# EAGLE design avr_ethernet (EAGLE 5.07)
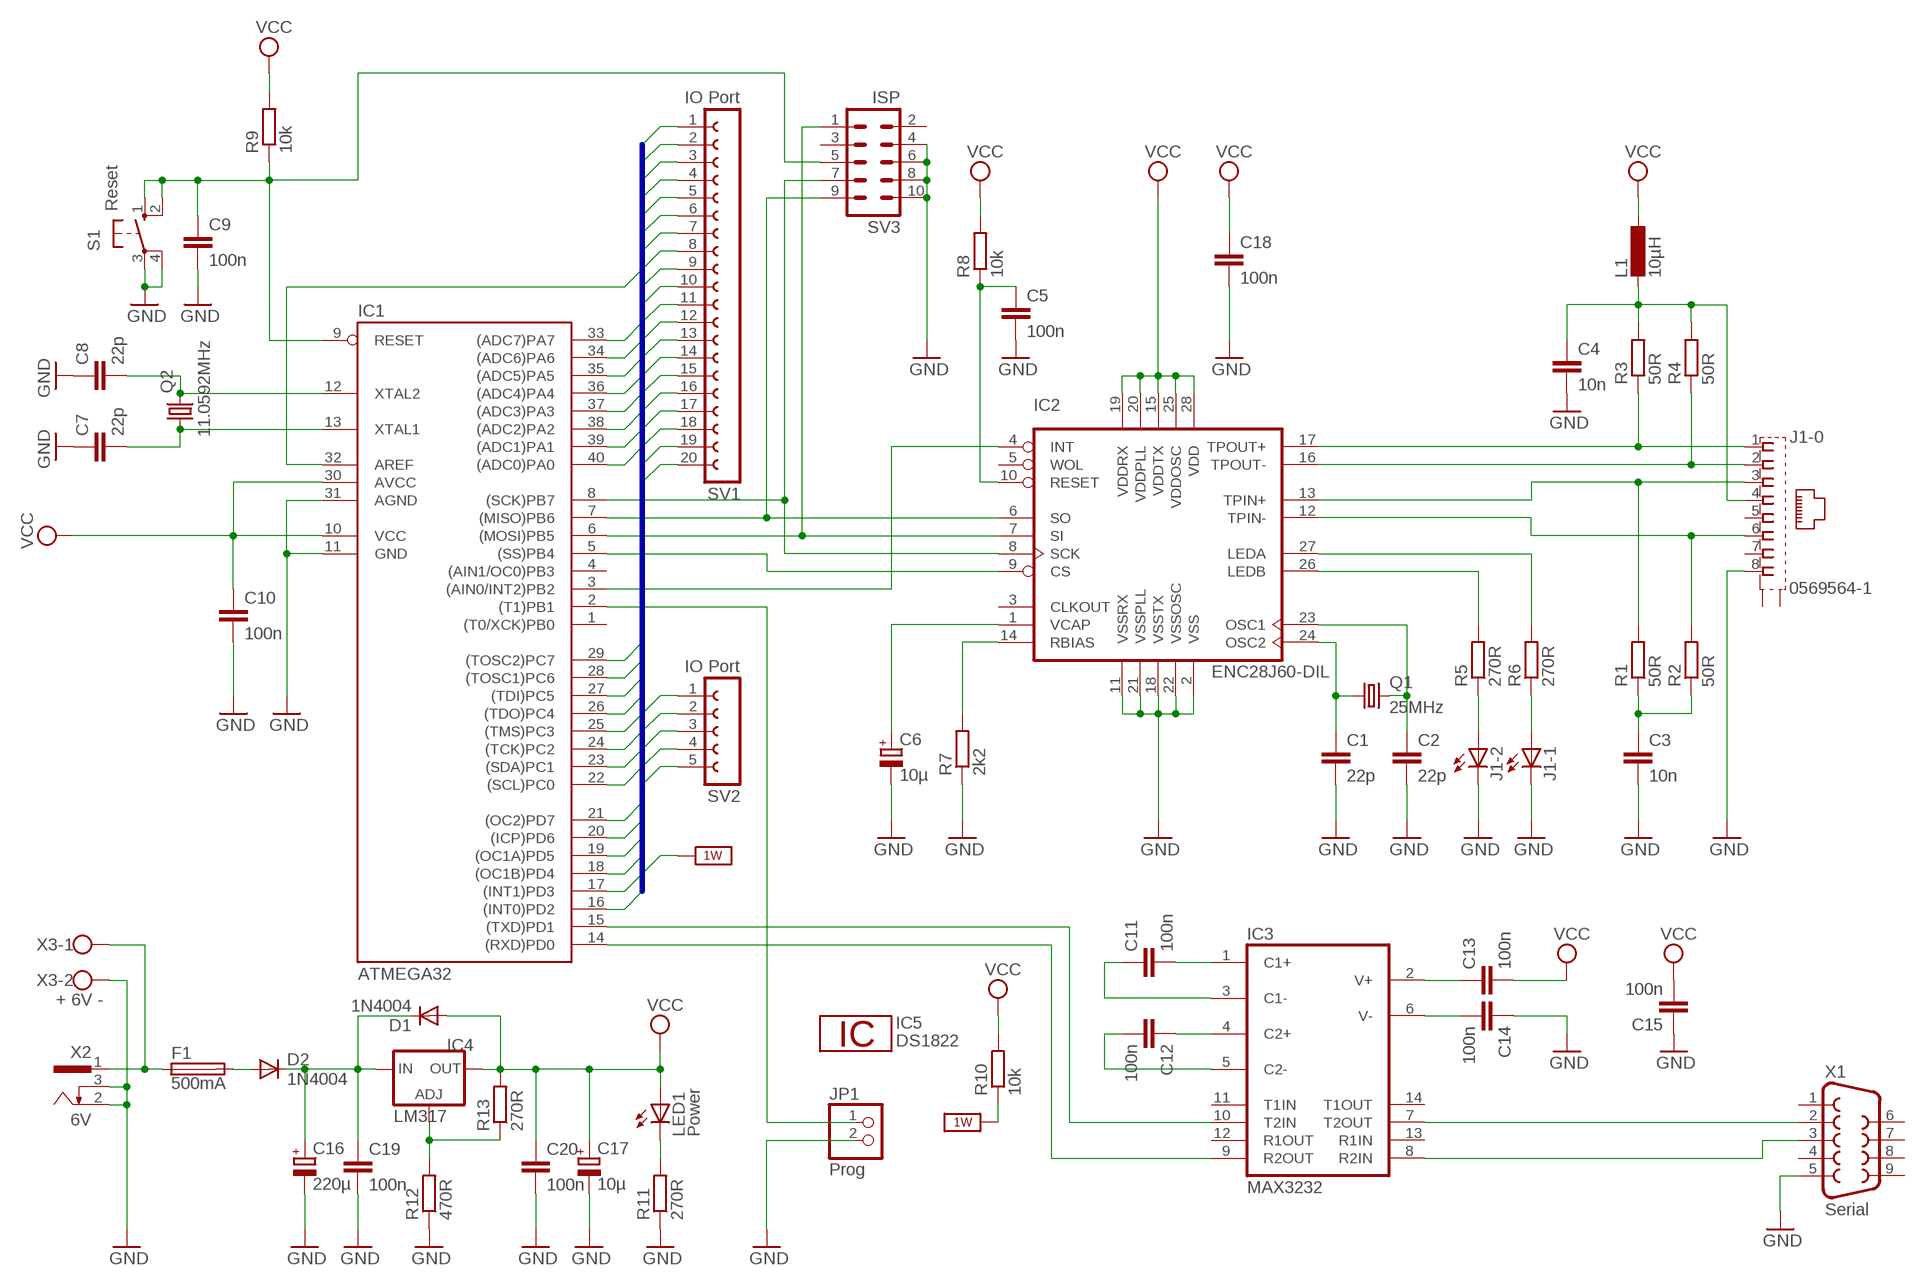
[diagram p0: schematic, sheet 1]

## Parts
C1  22p  C-EU025-025X050  [C025-025X050]
C2  22p  C-EU025-025X050  [C025-025X050]
C3  10n  C-EU025-025X050  [C025-025X050]
C4  10n  C-EU025-025X050  [C025-025X050]
C5  100n  C-EU025-025X050  [C025-025X050]
C6  10µ  CPOL-EUE2-5  [E2-5]
C7  22p  C-EU025-025X050  [C025-025X050]
C8  22p  C-EU025-025X050  [C025-025X050]
C9  100n  C-EU025-025X050  [C025-025X050]
C10  100n  C-EU025-025X050  [C025-025X050]
C11  100n  C-EU025-025X050  [C025-025X050]
C12  100n  C-EU025-025X050  [C025-025X050]
C13  100n  C-EU025-025X050  [C025-025X050]
C14  100n  C-EU025-025X050  [C025-025X050]
C15  100n  C-EU025-025X050  [C025-025X050]
C16  220µ  CPOL-EUE3.5-8  [E3,5-8]
C17  10µ  CPOL-EUE2-5  [E2-5]
C18  100n  C-EU025-025X050  [C025-025X050]
C19  100n  C-EU025-025X050  [C025-025X050]
C20  100n  C-EU025-025X050  [C025-025X050]
D1  1N4004  [DO41-10]
D2  1N4004  [DO41-10]
F1  500mA  PICOFUSE  [PICOFUSE]
IC1  ATMEGA32  MEGA32-P  [DIL40]
IC2  ENC28J60-DIL  [DIL28-3]
IC3  MAX3232  MAX232  [DIL16]
IC4  LM317  LM317TS  [317TS]
IC5  DS1822  [TO92-]
J1  0569564-1  [0569564]
JP1  Prog  PINHD-1X2  [1X02]
L1  10µH  L-EU0207/12  [0207/12]
LED1  Power  LED3MM  [LED3MM]
Q1  25MHz  CRYSTALHC49S  [HC49/S]
Q2  11.0592MHz  CRYSTALHC49S  [HC49/S]
R1  50R  R-EU_0207/10  [0207/10]
R2  50R  R-EU_0207/10  [0207/10]
R3  50R  R-EU_0207/10  [0207/10]
R4  50R  R-EU_0207/10  [0207/10]
R5  270R  R-EU_0207/10  [0207/10]
R6  270R  R-EU_0207/10  [0207/10]
R7  2k2  R-EU_0207/10  [0207/10]
R8  10k  R-EU_0207/12  [0207/12]
R9  10k  R-EU_0207/10  [0207/10]
R10  10k  R-EU_0207/10  [0207/10]
R11  270R  R-EU_0207/10  [0207/10]
R12  470R  R-EU_0207/10  [0207/10]
R13  270R  R-EU_0207/10  [0207/10]
S1  Reset  10-XX  [B3F-10XX]
SV1  IO Port  FE20-1  [FE20]
SV2  IO Port  FE05-1  [FE05-1]
SV3  ISP  ML10  [ML10]
X1  Serial  F09HP  [F09HP]
X2  6V  SCD-014A  [SCD-014-A]
X3  + 6V -  W237-102  [W237-102]

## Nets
1W: IC1.21((OC2)PD7) R10.1 SV1.20 ; supply symbol labelled 1W_SUP
AREF: IC1.32(AREF) SV1.9
GND: C1.2 C2.2 C3.2 C4.2 C5.2 C6.- C7.1 C8.1 C9.2 C10.2 C14.1 C15.1 C16.- C17.- C18.2 C19.2 C20.2 IC1.11(GND) IC1.31(AGND) IC2.2(VSS) IC2.11(VSSRX) IC2.18(VSSTX) IC2.21(VSSPLL) IC2.22(VSSOSC) J1.8 J1.C1(-1:C) J1.C2(-2:C) JP1.2 R7.1 R11.1 R12.1 S1.3(P) S1.4(P1) SV1.10 SV3.4 SV3.6 SV3.8 SV3.10 X1.5 X2.2 X2.3 X3.2
N$1: IC1.7((MISO)PB6) IC2.6(SO) SV3.9
N$2: IC1.6((MOSI)PB5) IC2.7(SI) SV3.1
N$3: IC1.8((SCK)PB7) IC2.8(SCK) SV3.7
N$4: IC2.17(TPOUT+) J1.1 R3.1
N$5: IC2.16(TPOUT-) J1.2 R4.1
N$6: IC2.13(TPIN+) J1.3 R1.2
N$7: IC2.12(TPIN-) J1.6 R2.2
N$8: C4.1 J1.4 L1.2 R3.2 R4.2
N$9: J1.A2(-2:A) R5.1
N$10: C3.1 R1.1 R2.1
N$11: J1.A1(-1:A) R6.1
N$12: IC2.26(LEDB) R5.2
N$13: IC2.27(LEDA) R6.2
N$14: C6.+ IC2.1(VCAP)
N$15: IC2.14(RBIAS) R7.2
N$16: IC1.3((AIN0/INT2)PB2) IC2.4(INT)
N$17: C1.1 IC2.24(OSC2) Q1.1
N$18: C2.1 IC2.23(OSC1) Q1.2
N$19: C5.1 IC2.10(RESET) R8.1
N$20: IC1.5((SS)PB4) IC2.9(CS)
N$21: C9.1 IC1.9(RESET) R9.1 S1.1(S) S1.2(S1) SV3.5
N$22: C7.2 IC1.13(XTAL1) Q2.1
N$23: C8.2 IC1.12(XTAL2) Q2.2
N$25: IC3.7(T2OUT) X1.2
N$26: IC3.8(R2IN) X1.3
N$27: C13.1 IC3.2(V+)
N$28: C14.2 IC3.6(V-)
N$30: C11.2 IC3.1(C1+)
N$31: C11.1 IC3.3(C1-)
N$32: C12.1 IC3.4(C2+)
N$33: C12.2 IC3.5(C2-)
N$34: IC1.15((TXD)PD1) IC3.10(T2IN)
N$35: IC1.14((RXD)PD0) IC3.9(R2OUT)
N$37: IC1.2((T1)PB1) JP1.1
N$42: D2.A F1.2
N$54: LED1.K(C) R11.2
N$55: F1.1 X2.1 X3.1
N$56: C16.+ C19.1 D1.C D2.C IC4.3(IN)
N$60: IC4.1(ADJ) R12.2 R13.1
PA0: IC1.40((ADC0)PA0) SV1.1
PA1: IC1.39((ADC1)PA1) SV1.2
PA2: IC1.38((ADC2)PA2) SV1.3
PA3: IC1.37((ADC3)PA3) SV1.4
PA4: IC1.36((ADC4)PA4) SV1.5
PA5: IC1.35((ADC5)PA5) SV1.6
PA6: IC1.34((ADC6)PA6) SV1.7
PA7: IC1.33((ADC7)PA7) SV1.8
PC0: IC1.22((SCL)PC0) SV1.19
PC1: IC1.23((SDA)PC1) SV1.18
PC2: IC1.24((TCK)PC2) SV1.17
PC3: IC1.25((TMS)PC3) SV1.16
PC4: IC1.26((TDO)PC4) SV1.15
PC5: IC1.27((TDI)PC5) SV1.14
PC6: IC1.28((TOSC1)PC6) SV1.13
PC7: IC1.29((TOSC2)PC7) SV1.12
PD2: IC1.16((INT0)PD2) SV2.1
PD3: IC1.17((INT1)PD3) SV2.2
PD4: IC1.18((OC1B)PD4) SV2.3
PD5: IC1.19((OC1A)PD5) SV2.4
PD6: IC1.20((ICP)PD6) SV2.5
VCC: C10.1 C13.2 C15.2 C17.+ C18.1 C20.1 D1.A IC1.10(VCC) IC1.30(AVCC) IC2.15(VDDTX) IC2.19(VDDRX) IC2.20(VDDPLL) IC2.25(VDDOSC) IC2.28(VDD) IC4.2(OUT) L1.1 LED1.A R8.2 R9.2 R10.2 R13.2 SV1.11
Unconnected: IC1.1((T0/XCK)PB0) IC1.4((AIN1/OC0)PB3) IC2.3(CLKOUT) IC2.5(WOL) IC3.11(T1IN) IC3.12(R1OUT) IC3.13(R1IN) IC3.14(T1OUT) J1.5 J1.7 J1.S1(-0:S1) J1.S2(-0:S2) SV3.2 SV3.3 X1.1 X1.4 X1.6 X1.7 X1.8 X1.9

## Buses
B$1:PA0,PA1,PA2,PA3,PA4,PA5,PA6,PA7,PC0,PC1,PC2,PC3,PC4,PC5,PC6,PC7,PD2,PD3,PD4,PD5,PD6,GND,VCC,AREF,1W

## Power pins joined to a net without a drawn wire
1W: IC5.2
GND: IC3.15(GND) IC5.1
VCC: IC3.16(VCC) IC5.3

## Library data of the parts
C1-C5 C7-C15 C18-C20 = rcl:C-EU: CAPACITOR, European symbol
C6 C16 C17 = rcl:CPOL-EU: POLARIZED CAPACITOR, European symbol
D1 D2 = diode:1N4004: DIODE
F1 = fuse:PICOFUSE: PICOFUSE
IC1 = atmel:MEGA32-P: MICROCONTROLLER 32 Kbytes FLASH 2 Kbytes SRAM 1 Kbytes EEPROM USART 8-channel 10 bit ADC Source: www.atmel.com .. doc2503.pdf
IC2 = microchip-enc28j60:ENC28J60-*: Microchip 10Mbit Eth. contoller with SPI interface
IC3 = maxim:MAX232: RS232 TRANSEIVER
IC4 = v-reg:LM317TS: VOLTAGE REGULATOR
IC5 = 1wire:DS1822: Econo Digital Thermometer This chip provides a onewire thermosensor with approx. 2°C accuracy. A programmable over/undertemperure alarm is available. Notes: Vdd must be applied for accurate measurements at low temperatures, as the parasite power circuit otherwise heats the sensor. If parasite power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
J1 = con-amp:0569564-*: MODULAR JACK 8 POS., RIGHT ANGLE, LOW PROFILE WITH LEDS Source: http://ecommas.tycoelectronics.com/.. 569564_K.pdf
JP1 = pinhead:PINHD-1X2: PIN HEADER
L1 = rcl:L-EU: INDUCTOR, European symbol
LED1 = led:LED: LED
Q1 Q2 = crystal:CRYSTAL: CRYSTAL
R1-R13 = rcl:R-EU_: RESISTOR, European symbol
S1 = switch-omron:10-XX: OMRON SWITCH
SV1 = con-lsta:FE20-1: FEMALE HEADER
SV2 = con-lsta:FE05-1: FEMALE HEADER
SV3 = con-harting-ml:ML10: HARTING
X1 = con-subd:F09: SUB-D
X2 = con-shiua-chyuan:SCD-014A: Power Jack 2.5mm
X3 = con-wago-500:W237-102: WAGO SCREW CLAMP

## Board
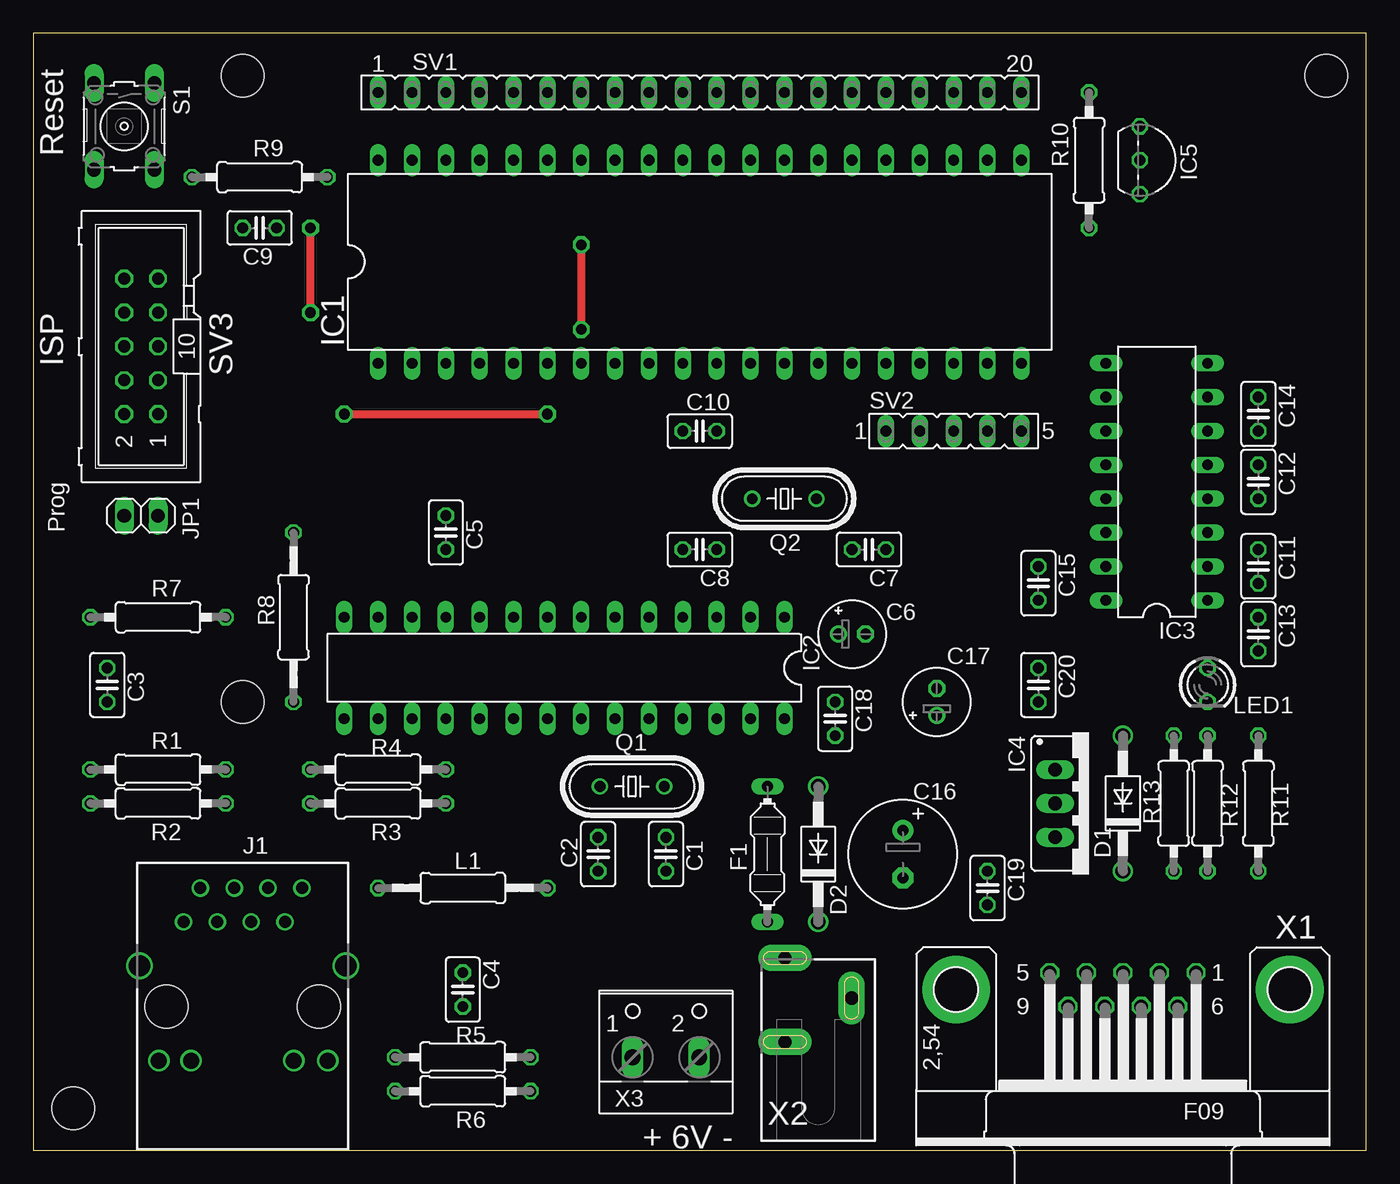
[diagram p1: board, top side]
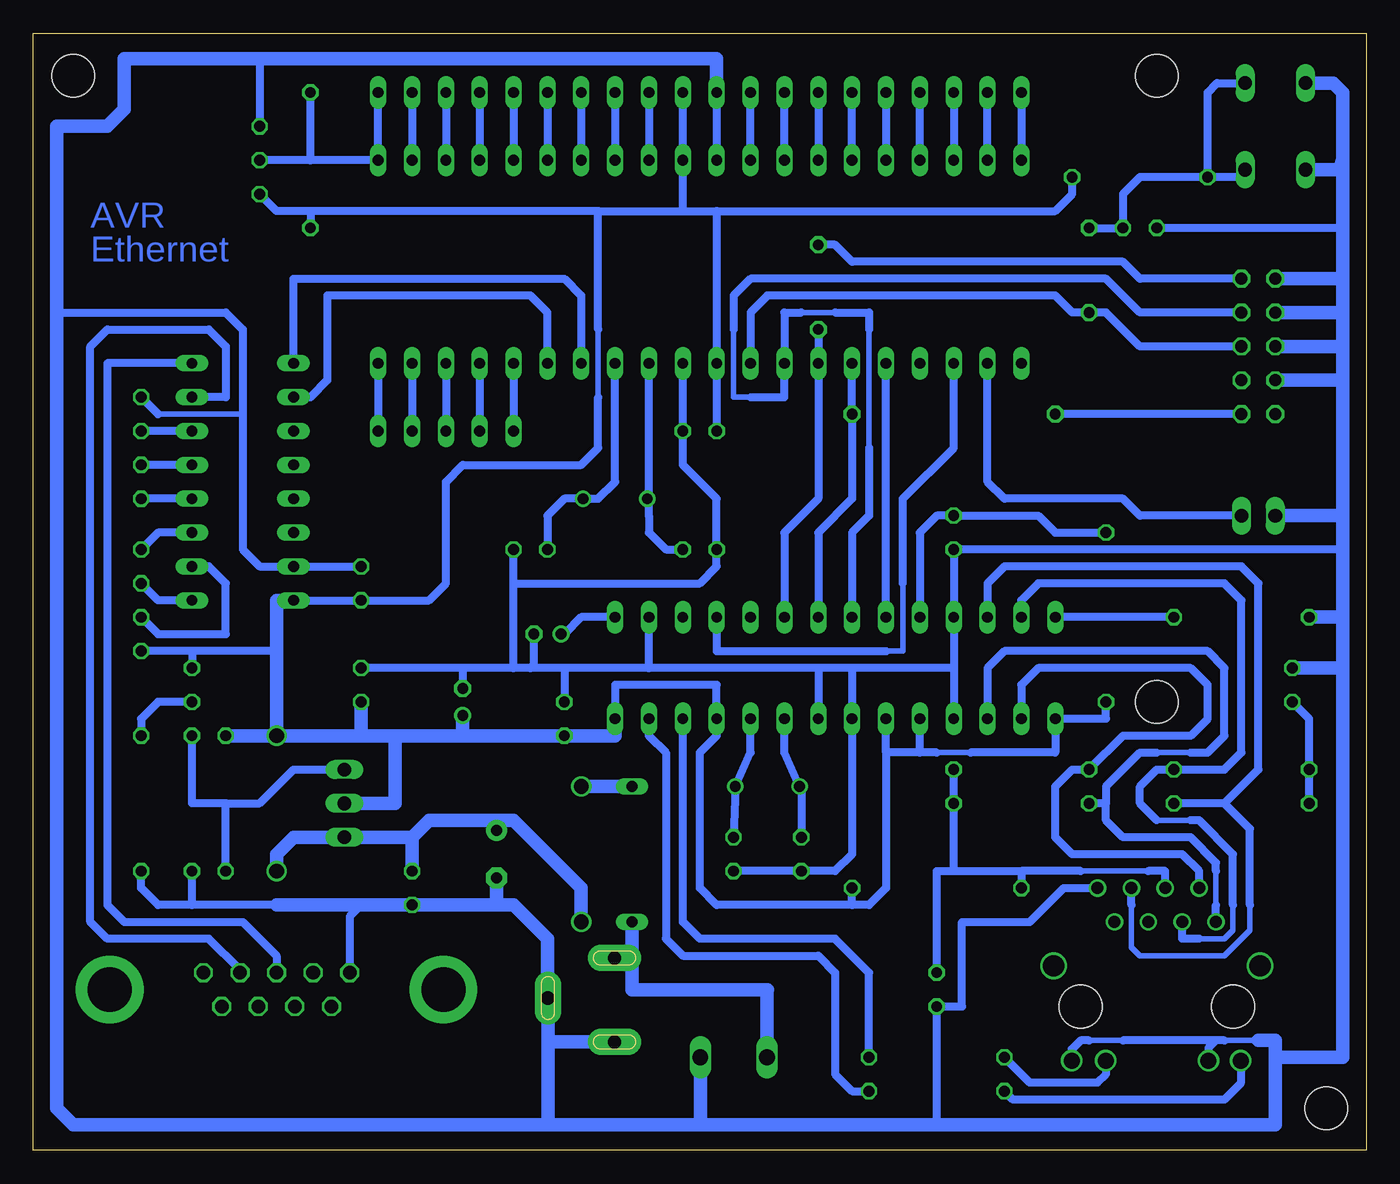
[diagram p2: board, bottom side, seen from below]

Size 100 x 83.81 mm. Coordinates in mm from the lower left corner, seen from the top.
Outline: 0,0 100,0 100,83.81 0,83.81 0,0
Copper layers (1*16): Top 0.035mm / dielectric 1.5mm / Bottom 0.035mm
Design rules "PCB-POOL": minimum track width 6mil, minimum drill 12mil, track to track 6mil, track to pad 6mil, pad to pad 6mil, via to via 6mil, smd to smd 6mil, copper to edge 20mil, drill to drill 8mil, minimum pad ring 8mil, minimum via ring 6mil, stop-mask expansion 3mil, vias tented up to drill 0mil, thermal gap 8mil
Holes 3.2 mm at 3.01,3.17 96.99,80.64 15.71,80.64 15.71,33.65

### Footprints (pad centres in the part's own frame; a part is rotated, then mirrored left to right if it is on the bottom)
C025-025X050 = drill 0.813 octagon: 1 -1.27,0; 2 1.27,0
E2-5 = drill 0.813 pad 1.27 round: + -1.016,0 | drill 0.813 pad 1.27 octagon: - 1.016,0
E3,5-8 = drill 0.813 pad 1.6 round: + -1.778,0 | drill 0.813 pad 1.6 octagon: - 1.778,0
DO41-10 = drill 1.118 round: A 5.08,0; C -5.08,0
PICOFUSE = drill 0.813 long: 1 -5.08,0; 2 5.08,0
DIL40 = drill 0.813 long: 1 -24.13,-7.62; 2 -21.59,-7.62; 3 -19.05,-7.62; 4 -16.51,-7.62; 5 -13.97,-7.62; 6 -11.43,-7.62; 7 -8.89,-7.62; 8 -6.35,-7.62; 9 -3.81,-7.62; 10 -1.27,-7.62; 11 1.27,-7.62; 12 3.81,-7.62; 13 6.35,-7.62; 14 8.89,-7.62; 15 11.43,-7.62; 16 13.97,-7.62; 17 16.51,-7.62; 18 19.05,-7.62; 19 21.59,-7.62; 20 24.13,-7.62; 21 24.13,7.62; 22 21.59,7.62; 23 19.05,7.62; 24 16.51,7.62; 25 13.97,7.62; 26 11.43,7.62; 27 8.89,7.62; 28 6.35,7.62; 29 3.81,7.62; 30 1.27,7.62; 31 -1.27,7.62; 32 -3.81,7.62; 33 -6.35,7.62; 34 -8.89,7.62; 35 -11.43,7.62; 36 -13.97,7.62; 37 -16.51,7.62; 38 -19.05,7.62; 39 -21.59,7.62; 40 -24.13,7.62
DIL28-3 = drill 0.813 long: 1 -16.51,-3.81; 2 -13.97,-3.81; 3 -11.43,-3.81; 4 -8.89,-3.81; 5 -6.35,-3.81; 6 -3.81,-3.81; 7 -1.27,-3.81; 8 1.27,-3.81; 9 3.81,-3.81; 10 6.35,-3.81; 11 8.89,-3.81; 12 11.43,-3.81; 13 13.97,-3.81; 14 16.51,-3.81; 15 16.51,3.81; 16 13.97,3.81; 17 11.43,3.81; 18 8.89,3.81; 19 6.35,3.81; 20 3.81,3.81; 21 1.27,3.81; 22 -1.27,3.81; 23 -3.81,3.81; 24 -6.35,3.81; 25 -8.89,3.81; 26 -11.43,3.81; 27 -13.97,3.81; 28 -16.51,3.81
DIL16 = drill 0.813 long: 1 -8.89,-3.81; 2 -6.35,-3.81; 3 -3.81,-3.81; 4 -1.27,-3.81; 5 1.27,-3.81; 6 3.81,-3.81; 7 6.35,-3.81; 8 8.89,-3.81; 9 8.89,3.81; 10 6.35,3.81; 11 3.81,3.81; 12 1.27,3.81; 13 -1.27,3.81; 14 -3.81,3.81; 15 -6.35,3.81; 16 -8.89,3.81
317TS = drill 1.016 long: 1 -2.54,-2.54; 2 0,-2.54; 3 2.54,-2.54
TO92- = drill 0.813 octagon: 1 -2.54,0; 2 0,0; 3 2.54,0
0569564 = drill 0.9 round: 1 -4.445,6.35; 2 -3.175,8.89; 3 -1.905,6.35; 4 -0.635,8.89; 5 0.635,6.35; 6 1.905,8.89; 7 3.175,6.35; 8 4.445,8.89 | drill 1.2 round: A1 -6.295,-4.066; A2 3.835,-4.066; C1 -3.882,-4.06; C2 6.375,-4.06 | drill 1.6 round: S1 -7.745,3.05; S2 7.745,3.05 | hole 3.25: -5.715,0; 5.715,0
1X02 = drill 1.016 long: 1 -1.27,0; 2 1.27,0
0207/12 = drill 0.813 octagon: 1 -6.35,0; 2 6.35,0
LED3MM = drill 0.813 octagon: A -1.27,0; K 1.27,0
HC49/S = drill 0.813 round: 1 -2.413,0; 2 2.413,0
0207/10 = drill 0.813 octagon: 1 -5.08,0; 2 5.08,0
B3F-10XX = drill 1.016 long: 1 -3.251,2.261; 2 3.251,2.261; 3 -3.251,-2.261; 4 3.251,-2.261
FE20 = drill 0.813 long: 1 -24.13,0; 2 -21.59,0; 3 -19.05,0; 4 -16.51,0; 5 -13.97,0; 6 -11.43,0; 7 -8.89,0; 8 -6.35,0; 9 -3.81,0; 10 -1.27,0; 11 1.27,0; 12 3.81,0; 13 6.35,0; 14 8.89,0; 15 11.43,0; 16 13.97,0; 17 16.51,0; 18 19.05,0; 19 21.59,0; 20 24.13,0
FE05-1 = drill 0.813 long: 1 -5.08,0; 2 -2.54,0; 3 0,0; 4 2.54,0; 5 5.08,0
ML10 = drill 0.914 octagon: 1 -5.08,-1.27; 2 -5.08,1.27; 3 -2.54,-1.27; 4 -2.54,1.27; 5 0,-1.27; 6 0,1.27; 7 2.54,-1.27; 8 2.54,1.27; 9 5.08,-1.27; 10 5.08,1.27
F09HP = drill 1.016 octagon: 1 -5.486,-1.27; 2 -2.743,-1.27; 3 0,-1.27; 4 2.743,-1.27; 5 5.486,-1.27; 6 -4.115,1.27; 7 -1.372,1.27; 8 1.372,1.27; 9 4.115,1.27 | drill 3.302 pad 5.08 round: G1 -12.522,0; G2 12.522,0
SCD-014-A = drill 1 pad 2 long: 1 -2.5,13.8; 2 -2.5,7.5; 3 2.5,10.8
W237-102 = drill 1.194 long: 1 -2.5,-1.27; 2 2.5,-1.27

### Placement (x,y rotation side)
C1  47.46,22.22 270 top
C2  42.38,22.22 270 top
C3  5.55,34.92 90 top
C4  32.22,12.06 270 top
C5  30.95,46.35 270 top
C6  61.43,38.73 0 top
C7  62.7,45.08 180 top
C8  50,45.08 0 top
C9  16.98,69.21 180 top
C10  50,53.97 0 top
C11  91.91,43.81 270 top
C12  91.91,50.16 90 top
C13  91.91,38.73 270 top
C14  91.91,55.24 270 top
C15  75.4,42.54 270 top
C16  65.24,22.22 270 top
C17  67.78,33.65 90 top
C18  60.16,32.38 90 top
C19  71.59,19.68 270 top
C20  75.4,34.92 90 top
D1  81.75,26.03 90 top
D2  58.89,22.22 90 top
F1  55.08,22.22 90 top
IC1  50,66.67 0 top
IC2  39.84,36.19 180 top
IC3  84.29,50.16 90 top
IC4  79.21,26.03 270 top
IC5  83.02,74.29 270 top
J1  15.71,10.79 0 top
JP1  8.09,47.62 180 top
L1  32.22,19.68 180 top
LED1  88.1,34.92 270 top
Q1  44.92,27.3 180 top
Q2  56.35,48.89 180 top
R1  9.36,28.57 0 top
R2  9.36,26.03 0 top
R3  25.87,26.03 0 top
R4  25.87,28.57 0 top
R5  32.22,6.98 0 top
R6  32.22,4.44 0 top
R7  9.36,40 0 top
R8  19.52,40 270 top
R9  16.98,73.02 0 top
R10  79.21,74.29 270 top
R11  91.91,26.03 90 top
R12  88.1,26.03 90 top
R13  85.56,26.03 90 top
S1  6.82,76.83 270 top
SV1  50,79.37 0 top
SV2  69.05,53.97 0 top
SV3  8.09,60.32 90 top
X1  81.75,12.06 180 top
X2  58.89,0.63 0 top
X3  47.46,8.25 0 top

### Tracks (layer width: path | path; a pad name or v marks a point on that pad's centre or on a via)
1W
  Bottom 0.61: 79.21,74.29 IC5.2 | 79.21,74.29 R10.1 | 79.21,74.29 IC1.21 SV1.20
AREF
  Bottom 0.61: IC1.32 SV1.9
GND
  Bottom 0.406: 30.95,36.19 IC2.11 | X2.3 61.39,10.79 61.43,10.79 | 65.24,1.9 61.39,1.94 | 61.39,8.25 61.43,8.25 61.31,8.13 | 84.29,55.24 90.64,55.24 | 1.74,75.56 2.3,73.58 | 8.09,8.25 10.63,8.25 | 18.25,8.25 20.79,8.25 | IC3.15 C15.1
  Bottom 0.61: 32.22,1.9 C4.2 30.31,10.79 30.31,17.14 25.23,17.14 22.7,19.68 J1.8 | 41.11,36.19 IC2.22 | 38.57,36.19 41.11,36.19 | C1.2 C2.2 39.84,20.95 38.57,22.22 IC2.21 38.57,36.19 | 30.95,36.19 IC2.18 | 41.11,36.19 53.81,36.19 | 53.81,36.19 60.16,36.19 | 53.81,36.19 IC2.2 | 60.16,36.19 C18.2 | 63.97,42.54 50,42.54 48.73,43.81 C8.1 48.73,48.89 51.27,51.43 C10.2 IC1.11 | 63.97,42.54 C7.1 | 63.97,36.19 63.97,42.54 | 30.95,36.19 38.57,36.19 | 30.95,36.19 C5.2 1.74,45.08 | 90.64,55.24 C14.1 | 98.26,62.86 85.56,62.86 84.29,61.59 84.29,55.24 84.29,45.08 83.02,43.81 IC3.15 C15.1 | R11.1 91.91,19.68 90.64,18.41 88.1,18.41 | 81.75,18.41 88.1,18.41 | 88.1,18.41 R12.1 | 60.16,36.19 62.7,36.19 | 62.7,36.19 63.97,36.19 | 63.97,36.19 67.78,36.19 | 67.78,36.19 C17.- | 67.78,36.19 C20.2 | C6.- 62.45,36.44 62.7,36.19 | J1.C2 22.08,7.59 21.42,8.25 20.79,8.25 | 10.63,8.25 11.27,8.25 | 11.27,8.25 18.25,8.25 | J1.C1 11.83,7.69 11.27,8.25 | X1.5 76.26,17.55 75.4,18.41 | 83.02,81.91 IC5.1 | 1.74,69.21 C9.2 | SV1.10 IC1.31
  Bottom 1.016: 1.74,36.19 C3.2 | 1.74,40 1.74,45.08 1.74,47.62 | 1.74,40 R7.1 | 1.74,36.19 1.74,40 | 50,1.9 32.22,1.9 6.82,1.9 6.82,6.98 | 50,1.9 65.24,1.9 96.99,1.9 98.26,3.17 98.26,62.86 98.26,76.83 94.45,76.83 93.18,78.1 93.18,81.91 83.02,81.91 48.73,81.91 SV1.10 | 61.39,1.94 61.39,8.25 61.39,10.79 | 61.31,8.13 X2.2 | 63.97,18.41 65.24,18.41 C16.- | 61.43,10.79 61.43,15.87 63.97,18.41 | 63.97,18.41 C19.2 75.4,18.41 81.75,18.41 | S1.3 2.45,80.08 1.74,79.37 1.74,75.56 1.74,69.21 1.74,65.4 | 1.74,47.62 1.74,57.78 | 1.74,57.78 1.74,60.32 | 1.74,60.32 1.74,62.86 | 1.74,62.86 1.74,65.4 | 2.3,73.58 S1.4 | 1.74,65.4 SV3.10 | 1.74,62.86 SV3.8 | 1.74,60.32 SV3.6 | 1.74,57.78 SV3.4 | 1.74,47.62 JP1.2 | X3.2 49.96,1.94 50,1.9 | 6.82,6.98 1.74,6.98 1.74,36.19 | 8.09,8.25 6.82,8.25 6.82,6.98
N$1  (via drill 0.8 pad 1.27)
  Top 0.61: v41.11,67.94 v41.11,61.59
  Bottom 0.61: IC2.6 43.65,46.35 41.11,48.89 IC1.7 v41.11,61.59 | SV3.9 16.98,65.4 18.25,66.67 38.57,66.67 39.84,67.94 v41.11,67.94
N$2  (via drill 0.8 pad 1.27)
  Top 0.61: v23.33,55.24 v38.57,55.24
  Bottom 0.61: IC2.7 41.11,46.35 38.57,48.89 v38.57,55.24 IC1.6 | SV3.1 v23.33,55.24
N$3
  Bottom 0.406: 37.3,61.59 37.3,52.7 | 42.38,62.86 39.84,62.86 | 46.19,56.51 47.46,56.51 47.46,61.59
  Bottom 0.61: IC2.8 38.57,46.35 37.3,47.62 37.3,52.7 | 37.3,61.59 37.3,62.86 39.84,62.86 | 42.38,62.86 43.65,62.86 IC1.8 43.65,56.51 46.19,56.51 | 47.46,61.59 47.46,64.13 46.19,65.4 19.52,65.4 16.98,62.86 SV3.7
N$4
  Bottom 0.406: 15.71,29.84 13.17,29.84 | 11.27,18.41 11.27,20.95
  Bottom 0.61: 19.52,26.03 R3.1 | 19.52,26.03 19.52,27.3 16.98,29.84 15.71,29.84 | 13.17,29.84 11.9,29.84 10.63,31.11 10.63,36.19 11.9,37.46 27.14,37.46 28.41,36.19 IC2.17 | J1.1 11.27,18.41 | 11.27,20.95 11.27,21.58 13.17,23.49 18.25,23.49 19.52,24.76 19.52,26.03
N$5
  Bottom 0.61: IC2.16 25.87,34.92 24.6,36.19 13.17,36.19 11.9,34.92 11.9,32.38 13.17,31.11 18.25,31.11 R4.1 22.06,28.57 23.33,27.3 23.33,23.49 22.06,22.22 13.81,22.22 12.54,20.95 J1.2
N$6
  Bottom 0.406: 12.54,15.87 10.63,15.87 10,16.5 10,18.41 | 13.17,24.76 15.71,24.76
  Bottom 0.61: IC2.13 25.87,41.27 24.6,42.54 10.63,42.54 9.36,41.27 9.36,29.84 10.63,28.57 R1.2 15.71,28.57 16.98,27.3 16.98,26.03 15.71,24.76 | J1.3 13.81,15.87 12.54,15.87 | 10,18.41 10,22.22 12.54,24.76 13.17,24.76
N$7
  Bottom 0.406: 17.61,18.41 17.61,15.24 16.98,14.6 10.63,14.6 8.73,16.5 8.73,18.41
  Bottom 0.61: 10.63,26.03 8.09,28.57 8.09,42.54 9.36,43.81 27.14,43.81 28.41,42.54 IC2.12 | 10.63,26.03 R2.2 | 17.61,18.41 J1.6 | 8.73,18.41 8.73,24.12 10.63,26.03
N$8
  Bottom 0.406: 16.34,20.95 21.42,20.95
  Bottom 0.61: 30.95,20.95 32.22,20.95 C4.1 | 30.95,20.95 R3.2 R4.2 | 25.87,20.95 L1.2 | 30.95,20.95 25.87,20.95 | J1.4 15.08,20.95 16.34,20.95 | 21.42,20.95 25.87,20.95
N$9
  Bottom 0.61: J1.A2 19.54,5.68 20.15,5.08 25.23,5.08 R5.1
N$10
  Bottom 0.61: R2.1 R1.1 4.28,32.38 C3.1
N$11
  Bottom 0.61: J1.A1 9.42,5.02 10.63,3.8 26.5,3.8 R6.1
N$12
  Bottom 0.61: R5.2 37.3,13.33 39.84,15.87 50,15.87 51.27,17.14 IC2.26
N$13
  Bottom 0.61: IC2.27 53.81,31.11 52.54,29.84 52.54,15.87 51.27,14.6 41.11,14.6 39.84,13.33 39.84,5.71 38.57,4.44 R6.2
N$14
  Bottom 0.61: IC2.1 58.89,40 60.16,38.73 C6.+
N$15
  Bottom 0.61: R7.2 IC2.14
N$16
  Bottom 0.406: 36.03,37.46 34.76,37.46 34.76,42.54
  Bottom 0.61: IC2.4 48.73,37.46 36.03,37.46 | 34.76,42.54 34.76,48.89 30.95,52.7 IC1.3
N$17
  Bottom 0.61: IC2.24 46.19,29.84 Q1.1 C1.1
N$18
  Bottom 0.61: IC2.23 43.65,29.84 Q1.2 42.38,27.3 C2.1
N$19
  Bottom 0.61: IC2.10 33.49,46.35 32.22,47.62 C5.1 24.6,47.62 23.33,46.35 R8.1
N$20
  Bottom 0.61: IC2.9 IC1.5
N$21  (via drill 0.8 pad 1.27)
  Top 0.61: v20.79,62.86 v20.79,69.21
  Bottom 0.61: IC1.9 46.19,62.86 44.92,64.13 23.33,64.13 22.06,62.86 v20.79,62.86 19.52,62.86 16.98,60.32 SV3.5 | R9.1 9.36,73.02 9.08,73.3 S1.2 | S1.1 11.19,80.08 11.9,79.37 R9.1 | v20.79,69.21 C9.1 18.25,71.75 16.98,73.02 R9.1
N$22
  Bottom 0.61: Q2.1 58.89,48.89 | Q2.1 57.62,48.89 56.35,50.16 IC1.13 | Q2.1 60.16,48.89 61.43,47.62 C7.2
N$23
  Bottom 0.406: Q2.2 53.81,47.62
  Bottom 0.61: IC1.12 53.81,47.62 53.81,46.35 52.54,45.08 C8.2
N$25
  Bottom 0.61: X1.2 84.49,13.53 86.83,15.87 94.45,15.87 95.72,17.14 95.72,60.32 94.45,61.59 86.83,61.59 85.56,60.32 85.56,56.51 IC3.7
N$26
  Bottom 0.61: IC3.8 94.45,59.05 94.45,18.41 93.18,17.14 84.29,17.14 81.75,14.6 X1.3
N$27
  Bottom 0.61: C13.1 90.64,38.73 85.56,38.73 85.56,42.54 86.83,43.81 IC3.2
N$28
  Bottom 0.61: IC3.6 C14.2
N$30
  Bottom 0.61: IC3.1 90.64,41.27 C11.2
N$31
  Bottom 0.61: IC3.3 90.64,46.35 C11.1
N$32
  Bottom 0.61: IC3.4 C12.1
N$33
  Bottom 0.61: IC3.5 C12.2
N$34
  Bottom 0.61: IC1.15 61.43,62.86 62.7,64.13 77.94,64.13 77.94,57.78 79.21,56.51 IC3.10
N$35
  Bottom 0.61: IC3.9 80.48,65.4 60.16,65.4 58.89,64.13 IC1.14
N$37
  Bottom 0.61: JP1.1 16.98,47.62 18.25,48.89 27.14,48.89 28.41,50.16 IC1.2
N$42
  Bottom 1.016: F1.2 D2.A
N$54
  Bottom 0.61: LED1.K 90.64,33.65 91.91,32.38 R11.2
N$55
  Bottom 0.61: 55.08,14.6 55.25,14.43
  Bottom 1.016: X2.1 55.25,14.43 55.08,14.26 55.08,12.06 44.92,12.06 44.96,12.02 X3.1 | 55.08,14.6 F1.1
N$56
  Bottom 1.016: D2.C 58.89,19.68 63.97,24.76 65.24,24.76 | 65.24,24.76 C16.+ | 65.24,24.76 70.32,24.76 71.59,23.49 | 71.59,23.49 C19.1 | D1.C 81.75,22.22 80.48,23.49 IC4.3 71.59,23.49
N$60
  Bottom 0.61: R13.1 85.56,26.03 | 85.56,26.03 88.1,26.03 R12.2 | 85.56,26.03 83.02,26.03 80.48,28.57 IC4.1
PA0
  Bottom 0.61: SV1.1 IC1.40
PA1
  Bottom 0.61: IC1.39 SV1.2
PA2
  Bottom 0.61: SV1.3 IC1.38
PA3
  Bottom 0.61: IC1.37 SV1.4
PA4
  Bottom 0.61: SV1.5 IC1.36
PA5
  Bottom 0.61: IC1.35 SV1.6
PA6
  Bottom 0.61: SV1.7 IC1.34
PA7
  Bottom 0.61: IC1.33 SV1.8
PC0
  Bottom 0.61: SV1.19 IC1.22
PC1
  Bottom 0.61: SV1.18 IC1.23
PC2
  Bottom 0.61: SV1.17 IC1.24
PC3
  Bottom 0.61: SV1.16 IC1.25
PC4
  Bottom 0.61: SV1.15 IC1.26
PC5
  Bottom 0.61: SV1.14 IC1.27
PC6
  Bottom 0.61: SV1.13 IC1.28
PC7
  Bottom 0.61: SV1.12 IC1.29
PD2
  Bottom 0.61: IC1.16 SV2.1
PD3
  Bottom 0.61: IC1.17 SV2.2
PD4
  Bottom 0.61: IC1.18 SV2.3
PD5
  Bottom 0.61: IC1.19 SV2.4
PD6
  Bottom 0.61: IC1.20 SV2.5
VCC
  Bottom 0.406: 57.62,56.51 57.62,61.59 | 29.68,29.84 32.22,29.84 | IC3.16 C15.2
  Bottom 0.61: 81.75,37.46 88.1,37.46 | 88.1,37.46 C13.2 | 57.62,70.48 51.27,70.48 | 57.62,61.59 57.62,70.48 | 57.62,56.51 57.62,52.7 58.89,51.43 67.78,51.43 69.05,50.16 69.05,42.54 70.32,41.27 C15.2 IC3.16 | R9.2 22.06,71.75 23.33,70.48 48.73,70.48 | 51.27,70.48 48.73,70.48 | IC2.28 56.35,34.92 48.73,34.92 IC2.25 48.73,31.11 50,29.84 50,19.68 48.73,18.41 38.57,18.41 | 36.03,29.84 36.03,19.68 37.3,18.41 38.57,18.41 | 38.57,18.41 L1.1 | 29.68,29.84 23.33,29.84 IC2.15 19.52,32.38 R8.2 | 32.22,29.84 33.49,29.84 | 33.49,29.84 36.03,29.84 | 36.03,29.84 IC2.20 | 33.49,29.84 IC2.19 | 88.1,37.46 LED1.A | 57.62,70.48 79.21,70.48 | 79.21,70.48 81.75,70.48 IC5.3 | 79.21,70.48 R10.2 | 48.73,70.48 IC1.10 C10.1 | 51.27,70.48 IC1.30 SV1.11
  Bottom 1.016: D1.A 81.75,37.46 81.75,41.27 IC3.16 | IC2.28 56.35,31.11 C18.1 67.78,31.11 | D1.A R13.2 | IC4.2 72.86,26.03 72.86,31.11 | 72.86,31.11 75.4,31.11 | 75.4,31.11 D1.A | 67.78,31.11 67.78,32.38 C17.+ | 67.78,31.11 72.86,31.11 | 75.4,31.11 C20.1

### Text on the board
Bottom: AVR | Ethernet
